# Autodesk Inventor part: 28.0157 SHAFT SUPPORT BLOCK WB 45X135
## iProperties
Created: 2007-06
Part Number: 28.0157 SHAFT SUPPORT BLOCK WB 45X135
Material: Aluminum-6061
Document SubType Name: Modeling
Designer: Andy Moles
Mass: 253.029 g
Surface Area: 602.815 cm^2
Volume: 93.3687 cm^3
Density: 2.71 g/cm^3
Author: Andy Moles
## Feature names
1. Extrusion1
2. Extrusion2
3. Extrusion3
